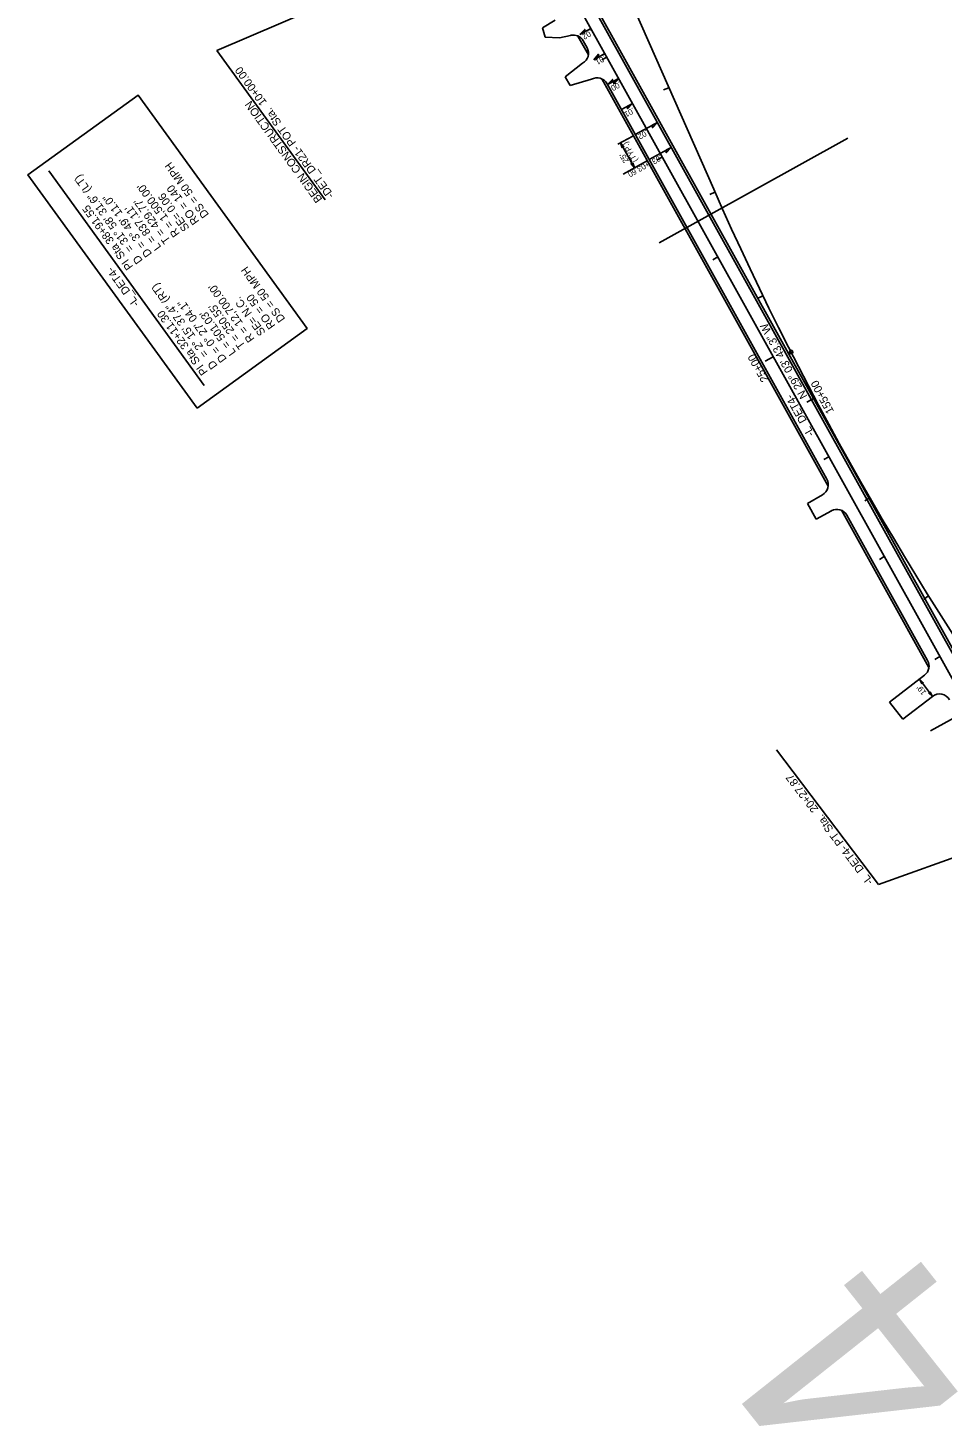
# Model space of a CAD drawing. Extents: x 473658 to 481584, y 489119 to 506230.
# Drawn here: x 475399 to 476199, y 500563 to 501786 of the extents above; entities that cross this region are included whole.
import ezdxf

# ---------------------------------------------------------------- set-up
doc = ezdxf.new("R2010")
doc.units = 0
for name, color, linetype in [('Exist Horizontal Alignment', 7, 'Continuous'), ('Prop Dimension', 7, 'Continuous'), ('Prop EOT', 7, 'Continuous'), ('Prop Grid Mask', 7, 'Continuous'), ('Prop Horizontal Alignment', 7, 'Continuous'), ('Prop Horizontal Alignment Curve and Spiral Data', 7, 'Continuous'), ('Prop Horizontal Alignment Direction Label', 7, 'Continuous'), ('Prop Horizontal Alignment Station Label', 7, 'Continuous'), ('Prop Horizontal Alignment Tick Label', 7, 'Continuous'), ('Prop Horizontal Alignment Tick Large', 7, 'Continuous'), ('Prop Horizontal Alignment Tick Small', 7, 'Continuous'), ('Prop Paved Shoulder', 7, 'Continuous'), ('Prop Superelevation  Arrow CELL', 7, 'Continuous'), ('Prop Superelevation Label', 7, 'Continuous'), ('Scratch_Level_1', 7, 'Continuous'), ('Scratch_Level_5', 7, 'Continuous'), ('Sheet Block Title CELL', 7, 'Continuous')]:
    doc.layers.add(name, color=color, linetype=linetype)

msp = doc.modelspace()

# ---------------------------------------------------------------- linework, layer by layer
at = {"layer": 'Exist Horizontal Alignment'}
for points in [[(476181.2, 501212.1), (476179.1, 501216.1), (476182.5, 501213), (476181.5, 501213)], [(476188.5, 501205.1), (476190.6, 501201), (476187.2, 501204.1), (476188.2, 501204.2)]]:
    msp.add_lwpolyline(points, close=True, dxfattribs=at)
at = {"layer": 'Prop Dimension'}
msp.add_line((476190.6, 501201), (476179.1, 501216.1), dxfattribs=at)
at = {"layer": 'Prop EOT'}
for p, q in [((476290.2, 501090.7), (475837.1, 501906.2)), ((475849.4, 501785.9), (475860.5, 501792.6)), ((475851.7, 501777.9), (475849.4, 501785.9)), ((475864.2, 501777.1), (475851.7, 501777.9)), ((475864.2, 501777.1), (475874, 501779.4)), ((475888.4, 501768.6), (475885.1, 501774.5)), ((475869.3, 501743.2), (475884.5, 501755)), ((475873.5, 501735.6), (475869.3, 501743.2)), ((475873.5, 501735.6), (475892.3, 501741)), ((476098.2, 501391), (475905.9, 501737.1)), ((476081.1, 501369.9), (476094.3, 501377.4)), ((476088.9, 501356.1), (476081.1, 501369.9)), ((476088.9, 501356.1), (476102.1, 501363.5)), ((476186.3, 501232.4), (476115.7, 501359.6)), ((476088.9, 501356.1), (476088.9, 501356.1)), ((476183.7, 501219.6), (476153, 501196)), ((476190.6, 501201), (476164.6, 501181)), ((476164.6, 501181), (476153, 501196))]:
    msp.add_line(p, q, dxfattribs=at)
for centre, start, end in [((475876.3, 501769.7), 29.062, 103.4582), ((475879.6, 501763.7), 299.062, 29.062), ((475897.1, 501732.2), 29.062, 119.062), ((476089.4, 501386.2), 299.062, 29.062), ((476106.9, 501354.7), 29.062, 119.062), ((476177.6, 501227.6), 307.5691, 29.062), ((476196.7, 501193.1), 29.062, 127.5691)]:
    msp.add_arc(centre, 10, start, end, dxfattribs=at)
at = {"layer": 'Prop Grid Mask'}
msp.add_lwpolyline([(475547.2, 501453.2), (475399.3, 501657.4), (475495.6, 501727.1), (475643.5, 501522.9)], close=True, dxfattribs=at)
at = {"layer": 'Prop Horizontal Alignment'}
for p, q in [((475999.2, 501644.7), (475755.7, 502196.2)), ((476280.6, 501085.4), (475827.5, 501900.8))]:
    msp.add_line(p, q, dxfattribs=at)
msp.add_arc((478615.6, 502799.6), 2860, 203.8164, 228.2476, dxfattribs=at)
at = {"layer": 'Prop Horizontal Alignment Station Label'}
for p, q in [((475553.4, 501473), (475417.4, 501660.8)), ((476143.2, 501036.5), (476054.1, 501154.2)), ((476281.9, 501086.1), (476143.2, 501036.5))]:
    msp.add_line(p, q, dxfattribs=at)
msp.add_circle((476066.9, 501502.3), 1.5, dxfattribs=at)
at = {"layer": 'Prop Horizontal Alignment Tick Large'}
for p, q in [((476051.3, 501498.1), (476044.3, 501494.2)), ((476087.6, 501462.3), (476080.5, 501458.5))]:
    msp.add_line(p, q, dxfattribs=at)
at = {"layer": 'Prop Horizontal Alignment Tick Small'}
for p, q in [((475905.6, 501760.3), (475901.2, 501757.9)), ((475959.9, 501733.6), (475955.3, 501731.6)), ((475954.1, 501672.9), (475949.8, 501670.5)), ((476000.3, 501642.2), (475995.7, 501640.1)), ((476002.7, 501585.5), (475998.3, 501583.1)), ((476042.3, 501551.4), (476037.8, 501549.3)), ((476099.9, 501410.7), (476095.5, 501408.2)), ((476135.8, 501374.7), (476131.5, 501372.2)), ((476148.4, 501323.3), (476144.1, 501320.8)), ((476187.2, 501288.9), (476182.9, 501286.2)), ((476197, 501235.8), (476192.6, 501233.4))]:
    msp.add_line(p, q, dxfattribs=at)
at = {"layer": 'Prop Paved Shoulder'}
for p, q in [((476292, 501091.7), (475838.8, 501907.1)), ((475889.6, 501762.3), (475880.4, 501778.8)), ((476099.3, 501384.8), (475901.2, 501741.4)), ((476187.5, 501226.2), (476111, 501363.9))]:
    msp.add_line(p, q, dxfattribs=at)
at = {"layer": 'Prop Superelevation  Arrow CELL'}
for points in [[(475882, 501780), (475886.3, 501784.6), (475886.1, 501782.2)], [(475894.2, 501758.1), (475898.5, 501762.8), (475898.2, 501760.4)], [(475906.3, 501736.3), (475910.6, 501740.9), (475910.4, 501738.5)], [(475916, 501741.6), (475911.7, 501736.9), (475911.9, 501739.4)], [(475928.1, 501719.7), (475923.8, 501715.1), (475924.1, 501717.5)], [(475949.9, 501703.2), (475945.6, 501698.6), (475945.8, 501701)], [(475919.1, 501681), (475917.6, 501685.3), (475920.5, 501681.8), (475919.6, 501681.9)], [(475962, 501681.4), (475957.7, 501676.7), (475958, 501679.1)], [(475928.3, 501667.8), (475929.8, 501663.5), (475926.9, 501667.1), (475927.9, 501666.9)]]:
    msp.add_lwpolyline(points, close=True, dxfattribs=at)
at = {"layer": 'Prop Superelevation Label'}
for p, q in [((475882, 501780), (475891.7, 501785.3)), ((475894.2, 501758.1), (475903.8, 501763.5)), ((475906.3, 501736.3), (475916, 501741.6)), ((475918.5, 501714.4), (475928.1, 501719.7)), ((475930.6, 501692.6), (475949.9, 501703.2)), ((475915.4, 501684.1), (475928.3, 501691.3)), ((475929.8, 501663.5), (475917.6, 501685.3)), ((475942.8, 501670.7), (475962, 501681.4)), ((475919.9, 501658), (475940.5, 501669.4))]:
    msp.add_line(p, q, dxfattribs=at)
at = {"layer": 'Scratch_Level_1'}
for p in [(475782, 501859.2), (475659.2, 501635.5)]:
    msp.add_line(p, (475564.5, 501766.2), dxfattribs=at)
at = {"layer": 'Scratch_Level_5'}
for p, q in [((475951.5, 501597.8), (476116.5, 501689.5)), ((476188.8, 501170.8), (476353.8, 501262.5))]:
    msp.add_line(p, q, dxfattribs=at)

# ---------------------------------------------------------------- texts
at = {"layer": 'Prop Dimension'}
msp.add_text("19'", height=5, rotation=127.5691, dxfattribs=at).set_placement((476185.5, 501204.5))
at = {"layer": 'Prop Horizontal Alignment Curve and Spiral Data'}
for s, p in [('DS = 50 MPH', (475557.9, 501622.6)), ('= 31%%d 58\' 31.6" (LT)', (475492.2, 501592.7)), ("R = 1,500.00'", (475532.4, 501605.9)), ('SE= 0.06', (475540.9, 501610.9)), ('RO = 140', (475549.4, 501616.7)), ('PI Sta 38+91.55', (475491.5, 501577.1)), ('D = 3%%d 49\' 11.0"', (475508.1, 501588.3)), ("L = 837.11'", (475516.2, 501594.2)), ("T = 429.77'", (475524.3, 501600)), ('D', (475500, 501582.4)), ('DS = 50 MPH', (475624.6, 501531.3)), ('= 2%%d 15\' 37.4" (RT)', (475557.6, 501500.6)), ("R = 12,700.00'", (475597.8, 501513.8)), ('D = 0%%d 27\' 04.1"', (475573.5, 501496.2)), ("T = 250.55'", (475589.7, 501507.9)), ('SE= N.C.', (475607.5, 501519.6)), ('RO = 50', (475616, 501525.4)), ('PI Sta 32+11.30', (475556.9, 501485)), ("L = 501.03'", (475581.6, 501502.1)), ('D', (475565.4, 501490.3))]:
    msp.add_text(s, height=7, rotation=125.9074, dxfattribs=at).set_placement(p)
at = {"layer": 'Prop Horizontal Alignment Direction Label'}
for s, p in [('N 29%%d 03\' 43.3" W', (476081.4, 501463.7)), ('-L_DET4-', (476087.4, 501430.6))]:
    msp.add_text(s, height=7, rotation=119.062, dxfattribs=at).set_placement(p)
at = {"layer": 'Prop Horizontal Alignment Station Label'}
for s, rotation, p in [('-L_DET4-', 125.9074, (475497, 501544.7)), ('-L_DET4- PT Sta.  20+27.87', 127.1236, (476139.1, 501039.1))]:
    msp.add_text(s, height=7, rotation=rotation, dxfattribs=at).set_placement(p)
at = {"layer": 'Prop Horizontal Alignment Tick Label'}
for s, rotation, p in [('25+00', 119.062, (476047.4, 501478.4)), ('155+00', 117.8788, (476104.6, 501450.5))]:
    msp.add_text(s, height=7, rotation=rotation, dxfattribs=at).set_placement(p)
at = {"layer": 'Prop Superelevation Label'}
for s, rotation, p in [('.02', 209.062, (475891.7, 501784.3)), ('.01', 209.062, (475903.2, 501762.1)), ('.00', 209.062, (475916.8, 501739.3)), ('.01', 209.062, (475928.4, 501716.3)), ('.02', 209.062, (475940.3, 501696.9)), ('(TYP.)', 119.0709, (475932.9, 501670)), ("25'", 119.0709, (475925, 501669.3)), ('+03.60', 209.2384, (475941.5, 501669.5)), ('.03', 209.062, (475952.6, 501675.1))]:
    msp.add_text(s, height=5, rotation=rotation, dxfattribs=at).set_placement(p)
at = {"layer": 'Scratch_Level_1'}
for s, p in [('-DET_DR21- POT Sta.  10+00.00', (475667.4, 501639.6)), ('BEGIN CONSTRUCTION', (475657.1, 501636))]:
    msp.add_text(s, height=7, rotation=125.9074, dxfattribs=at).set_placement(p)
at = {"layer": 'Sheet Block Title CELL'}
msp.add_text('4', height=200, rotation=128.4488, dxfattribs=at).set_placement((476252, 500616.2))

doc.saveas('drawing.dxf')
